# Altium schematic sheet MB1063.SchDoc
size A4; Revision: B.1(PCB.SCH)
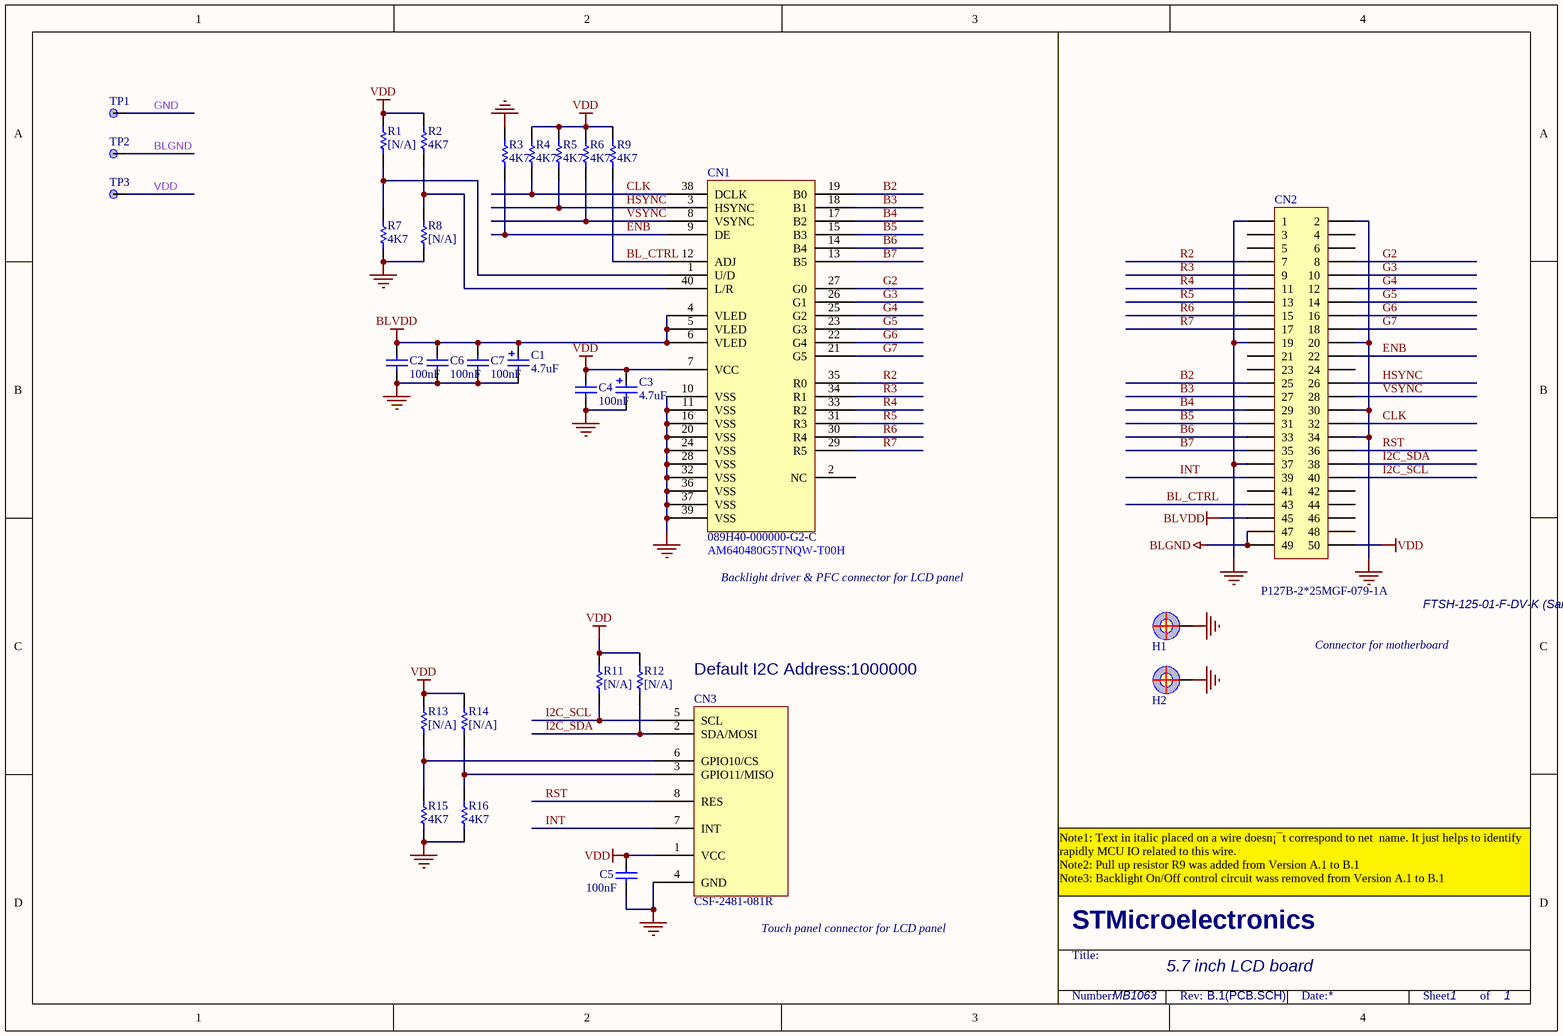
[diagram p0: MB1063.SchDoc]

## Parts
C1  4.7uF  [TAN-A]
C2  100nF  [0603C]
C3  4.7uF  [TAN-A]
C4  100nF  [0603C]
C5  100nF  [0603C]
C6  100nF  [0603C]
C7  100nF  [0603C]
CN1  089H40-000000-G2-C  [FPC40_0R5_089H40LY-FPC_REV]
CN2  P127B-2*25MGF-079-1A  [FTSH-125-01-F-DV]
CN3  CSF-2481-081R  [FPC8_0R5_089H08_LY-FPC_REV]
H1  POSITION HOLE  [HOLE_C9D4R5]  (value not drawn)
H2  POSITION HOLE  [HOLE_C9D4R5]  (value not drawn)
R1  [N/A]  [0603R]
R2  4K7  [0603R]
R3  4K7  [0603R]
R4  4K7  [0603R]
R5  4K7  [0603R]
R6  4K7  [0603R]
R7  4K7  [0603R]
R8  [N/A]  [0603R]
R9  4K7  [0603R]
R11  [N/A]  [0603R]
R12  [N/A]  [0603R]
R13  [N/A]  [0603R]
R14  [N/A]  [0603R]
R15  4K7  [0603R]
R16  4K7  [0603R]
TP1  (no value)  [TP]
TP2  (no value)  [TP]
TP3  (no value)  [TP]

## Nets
BLGND: CN2.47 CN2.49 TP2.1
BLVDD: C1.1 C2.2 C6.2 C7.2 CN1.4(VLED) CN1.5(VLED) CN1.6(VLED) CN2.45
GND: C1.2 C2.1 C3.2 C4.1 C5.1 C6.1 C7.1 CN1.10(VSS) CN1.11(VSS) CN1.16(VSS) CN1.20(VSS) CN1.24(VSS) CN1.28(VSS) CN1.32(VSS) CN1.36(VSS) CN1.37(VSS) CN1.39(VSS) CN2.1 CN2.2 CN2.19 CN2.20 CN2.30 CN2.34 CN2.37 CN3.4(GND) H1.1 H2.1 R3.1 R7.2 R8.2 R15.2 R16.2 TP1.1
VDD: C3.1 C4.2 C5.2 CN1.7(VCC) CN2.50 CN3.1(VCC) R1.1 R2.1 R4.1 R5.1 R6.1 R9.1 R11.1 R12.1 R13.1 R14.1 TP3.1
B2: CN1.19(B0) CN2.25
B3: CN1.18(B1) CN2.27
B4: CN1.17(B2) CN2.29
B5: CN1.15(B3) CN2.31
B6: CN1.14(B4) CN2.33
B7: CN1.13(B5) CN2.35
BL_CTRL: CN1.12(ADJ) CN2.43 R9.2
CLK: CN1.38(DCLK) CN2.32 R4.2
ENB: CN1.9(DE) CN2.22 R3.2
G2: CN1.27(G0) CN2.8
G3: CN1.26(G1) CN2.10
G4: CN1.25(G2) CN2.12
G5: CN1.23(G3) CN2.14
G6: CN1.22(G4) CN2.16
G7: CN1.21(G5) CN2.18
HSYNC: CN1.3(HSYNC) CN2.26 R5.2
I2C_SCL: CN2.40 CN3.5(SCL) R11.2
I2C_SDA: CN2.38 CN3.2(SDA/MOSI) R12.2
INT: CN2.39 CN3.7(INT)
R2: CN1.35(R0) CN2.7
R3: CN1.34(R1) CN2.9
R4: CN1.33(R2) CN2.11
R5: CN1.31(R3) CN2.13
R6: CN1.30(R4) CN2.15
R7: CN1.29(R5) CN2.17
RST: CN2.36 CN3.8(RES)
VSYNC: CN1.8(VSYNC) CN2.28 R6.2
NetCN1_1: CN1.1(U/D) R1.2 R7.1
NetCN1_40: CN1.40(L/R) R2.2 R8.1
NetCN3_3: CN3.3(GPIO11/MISO) R14.2 R16.1
NetCN3_6: CN3.6(GPIO10/CS) R13.2 R15.1

Not connected (* = marked no-connect by the designer): CN1 2(NC); CN2 3 4 5 6 21 23 24 41 42 44 46 48

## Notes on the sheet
- (near CN1) AM640480G5TNQW-T00H
- Backlight driver & PFC connector for LCD panel
- Connector for motherboard
- FTSH-125-01-F-DV-K (Samtec)
- Default I2C Address:1000000
- Note1: Text in italic placed on a wire doesn¡¯t correspond to net  name. It just helps to identify rapidly MCU IO related to this wire.
  Note2: Pull up resistor R9 was added from Version A.1 to B.1
  Note3: Backlight On/Off control circuit wass removed from Version A.1 to B.1
- Touch panel connector for LCD panel
- 5.7 inch LCD board
- MB1063
- 1

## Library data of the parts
C1 C3 = Cap Pol1: Polarized Capacitor (Radial); Value: 100pF
C2 C4-C7 = CAP: Capacitor; Value: 100pF
CN2 = Header 25X2: Header, 26-Pin, Dual row
R1-R9 R11-R16 = Res1: Resistor; Value: 1K
TP1-TP3 = TP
